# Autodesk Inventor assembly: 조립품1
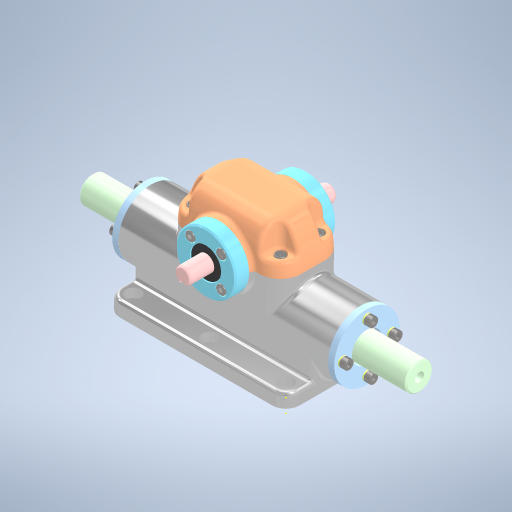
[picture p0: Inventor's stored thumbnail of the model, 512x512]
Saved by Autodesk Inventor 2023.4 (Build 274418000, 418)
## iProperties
Created: 2024-06
Part Number: 조립품1
Document SubType Name: Assembly
Designer: EDU-001
Author: EDU-001
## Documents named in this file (13)
- C:\Users\EDU-001\Desktop\740604v1014\조립품1.iam
- C:\Users\EDU-001\Desktop\740604v1014\본체.ipt
- C:\Users\EDU-001\Desktop\740604v1014\깊은 홈 볼 베어링 6901.ipt
- C:\Users\EDU-001\Desktop\740604v1014\랙.ipt
- C:\Users\EDU-001\Desktop\740604v1014\베어링 커버.ipt
- C:\Users\EDU-001\Desktop\740604v1014\부시 커버.ipt
- C:\Users\EDU-001\Desktop\740604v1014\스프링 와셔 M4.ipt
- C:\Users\EDU-001\Desktop\740604v1014\오일레스 부시.ipt
- C:\Users\EDU-001\Desktop\740604v1014\오일실 12 22 7.ipt
- C:\Users\EDU-001\Desktop\740604v1014\윗커버.ipt
- C:\Users\EDU-001\Desktop\740604v1014\육각 소켓 머리 볼트 M4x10.ipt
- C:\Users\EDU-001\Desktop\740604v1014\칼라.ipt
- C:\Users\EDU-001\Desktop\740604v1014\피니언.ipt
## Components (1 placed, 1 different names)
1. 피니언:1
## Named parameters: d64_d60 = 0, d65_d61 = 0, d66_d60 = 0, d67_d61 = 0, d68_d60 = 0, d69_d61 = 0
